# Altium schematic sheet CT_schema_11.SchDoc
size 274 x 160 mm
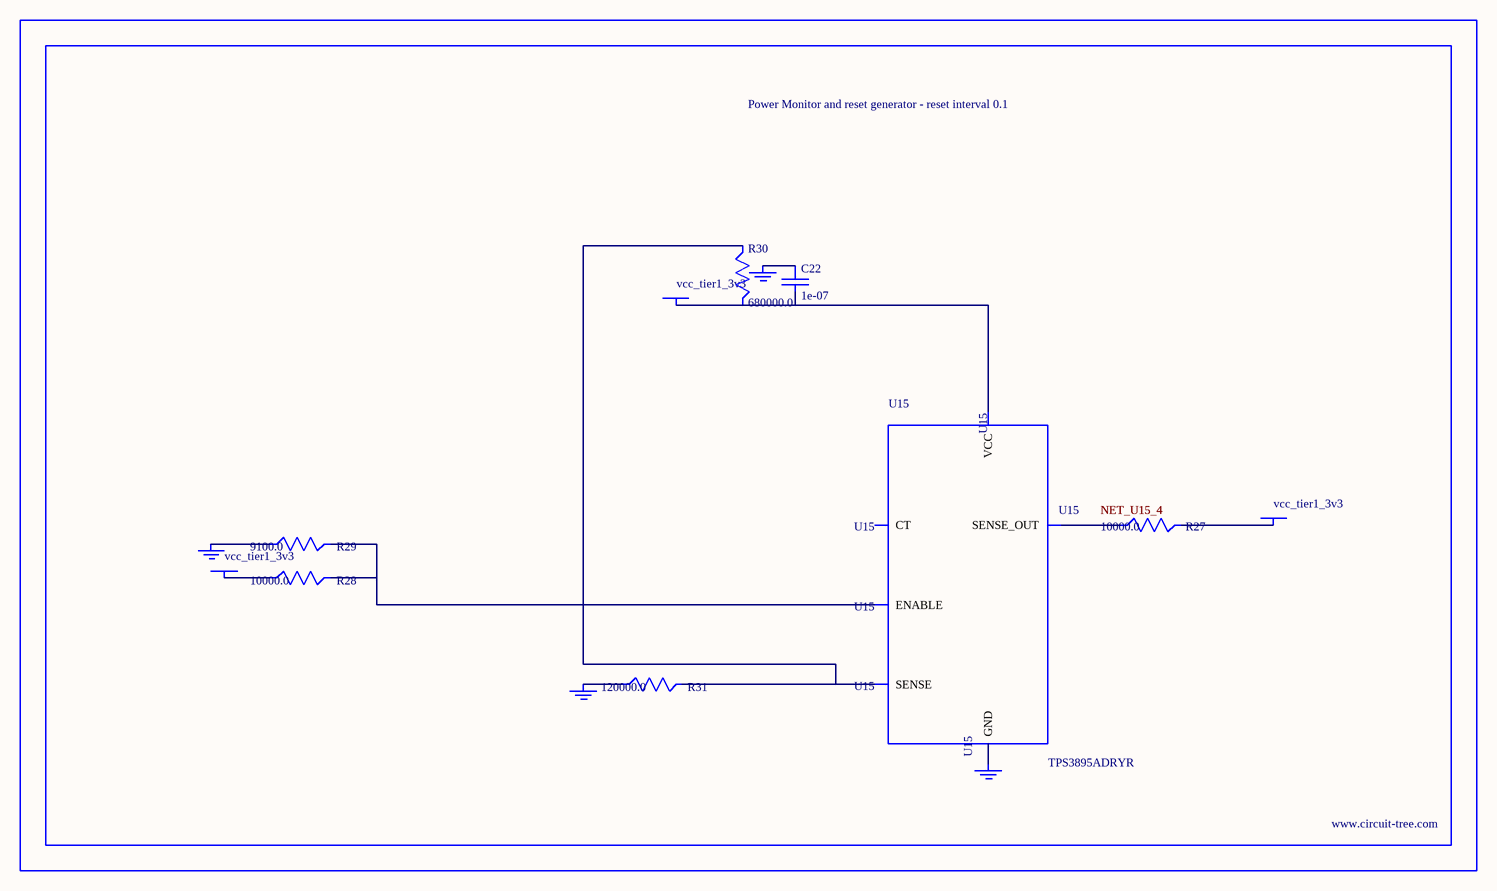
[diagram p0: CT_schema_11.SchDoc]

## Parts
BORDER10  (no value)
C22  1e-07  [C0402]
GND_INSTANCE_10_0  (no value)
GND_INSTANCE_10_1  (no value)
GND_INSTANCE_10_2  (no value)
GND_INSTANCE_10_3  (no value)
POWER_INSTANCE_10_0  vcc_tier1_3v3
POWER_INSTANCE_10_1  vcc_tier1_3v3
POWER_INSTANCE_10_2  vcc_tier1_3v3
R27  10000.0  [R0603]
R28  10000.0  [R0603]
R29  9100.0  [R0603]
R30  680000.0  [R0603]
R31  120000.0  [R0603]
U15  TPS3895ADRYR  [SON-6]

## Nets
NetC22_1: C22.1 GND_INSTANCE_10_2.0(GND)
NetC22_2: C22.2 POWER_INSTANCE_10_2.0(PWR) R30.2 U15.6(VCC)
NetGND_INSTANCE_10_0_0: GND_INSTANCE_10_0.0(GND) R29.1
NetGND_INSTANCE_10_1_0: GND_INSTANCE_10_1.0(GND) R31.1
NetGND_INSTANCE_10_3_0: GND_INSTANCE_10_3.0(GND) U15.2(GND)
NetPOWER_INSTANCE_10_0_0: POWER_INSTANCE_10_0.0(PWR) R28.1
NetPOWER_INSTANCE_10_1_0: POWER_INSTANCE_10_1.0(PWR) R27.2
NetR27_1: R27.1 U15.4(SENSE_OUT)
NetR28_2: R28.2 R29.2 U15.1(ENABLE)
NetR30_1: R30.1 R31.2 U15.3(SENSE)

Not connected (* = marked no-connect by the designer): U15 5(CT)

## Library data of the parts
BORDER10 = BORDER_PAGE10
C22 = C0402C104K3RACTU
GND_INSTANCE_10_0-GND_INSTANCE_10_3 = GND
POWER_INSTANCE_10_0-POWER_INSTANCE_10_2 = PWR
R27 R28 = RC0603JR-0710KL
R29 = RC0603JR-079K1L
R30 = RC0603JR-07680KL
R31 = RC0603JR-07120KL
